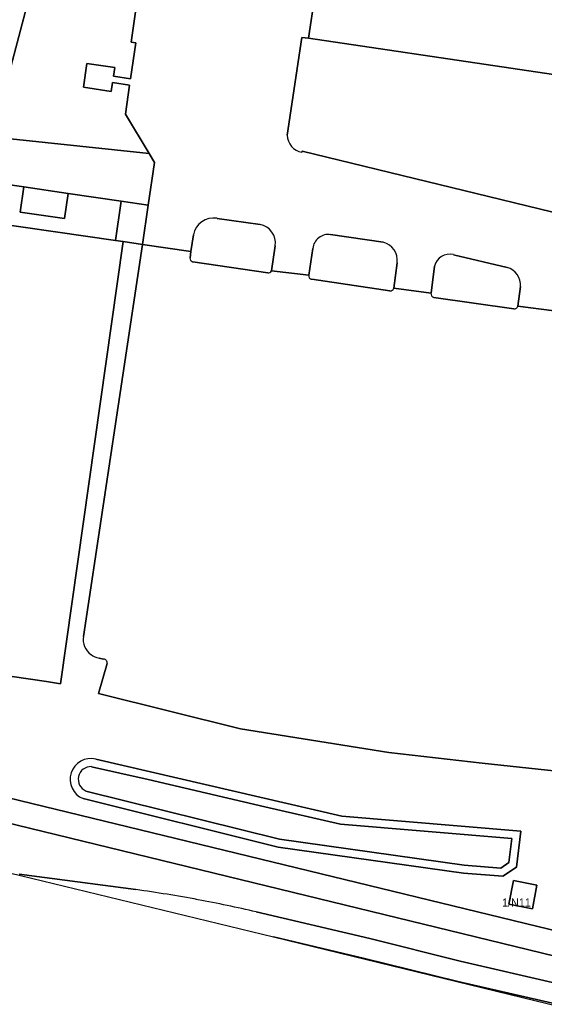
# Model space of a CAD drawing. Extents: x 163043 to 165076, y 382019 to 382874.
# Drawn here: x 164887 to 164952.3, y 382019.4 to 382142.4 of the extents above; entities that cross this region are included whole.
import ezdxf

# ---------------------------------------------------------------- set-up
doc = ezdxf.new("R2010")
doc.units = 0
for name, color, linetype in [('IMGEO_Berm_groen', 7, 'Continuous'), ('IMGEO_Erf', 7, 'Continuous'), ('IMGEO_Fietspad_gesloten', 7, 'Continuous'), ('IMGEO_Groenvoorziening', 7, 'Continuous'), ('IMGEO_Hek', 7, 'Continuous'), ('IMGEO_Oever', 7, 'Continuous'), ('IMGEO_Pand', 7, 'Continuous'), ('IMGEO_Pand_nummerreeks', 7, 'Continuous'), ('IMGEO_Parkeervlak_open', 7, 'Continuous'), ('IMGEO_Rijbaan_lokaal_gesloten', 7, 'Continuous'), ('IMGEO_Rijbaan_lokaal_open', 7, 'Continuous'), ('IMGEO_Verkeerseiland_groen', 7, 'Continuous'), ('IMGEO_Voetpad_open', 7, 'Continuous'), ('IMGEO_Waterloop', 7, 'Continuous')]:
    doc.layers.add(name, color=color, linetype=linetype)

msp = doc.modelspace()

# ---------------------------------------------------------------- linework, layer by layer
at = {"layer": 'IMGEO_Berm_groen'}
for points in [[(164916.45, 382031.48), (164930.58, 382028.18), (164941.81, 382025.37), (164953.88, 382022.57), (164956.12, 382022.19), (164956.22, 382022.18), (164956.8, 382025), (164956.85, 382025.19), (164602.85, 382111.38), (164599.99, 382112.07), (164598.73, 382112.35), (164592.38, 382113.1), (164591, 382106.94)], [(164886.96, 382036.16), (164901.48, 382034.26)], [(164955.57, 382019.38), (164955.65, 382019.7), (164955.47, 382019.72), (164953.3, 382020.13), (164941.52, 382022.81), (164929.91, 382025.67), (164918.61, 382028.36), (164954.36, 382019.67), (164955.57, 382019.38)]]:
    msp.add_lwpolyline(points, dxfattribs=at)
for centre, radius, start, end in [((164878.38, 381867.91), 167.94, 79.4249, 82.0936), ((164878.35, 381867.42), 168.43, 76.9252, 79.4441)]:
    msp.add_arc(centre, radius, start, end, dxfattribs=at)
at = {"layer": 'IMGEO_Erf'}
for points in [[(164884.69, 382132.02), (164887.33, 382141.95), (164891.24, 382156.72), (164892.95, 382163.15), (164895.44, 382168.42), (164899.25, 382173.36), (164897.45, 382173.61), (164897.75, 382175.55), (164892.78, 382176.32), (164891.37, 382170.91), (164884.17, 382143.37)], [(164910.89, 382163.64), (164907.37, 382164.18), (164908.63, 382172.08), (164899.25, 382173.36), (164895.44, 382168.42), (164892.95, 382163.15), (164891.24, 382156.72), (164887.33, 382141.95), (164884.69, 382132.02), (164885.86, 382127.64), (164903.11, 382125.8), (164900.16, 382130.69), (164900.69, 382134.32), (164898.56, 382134.63), (164898.4, 382133.54), (164894.94, 382134.05), (164895.38, 382137.02), (164898.84, 382136.51), (164898.68, 382135.42), (164900.81, 382135.11), (164901.46, 382139.57)], [(164901.46, 382139.57), (164900.87, 382139.65), (164901.63, 382144.87), (164890.74, 382146.43), (164892.91, 382161.18), (164903.55, 382159.66), (164903.4, 382158.01)]]:
    msp.add_lwpolyline(points, dxfattribs=at)
at = {"layer": 'IMGEO_Fietspad_gesloten'}
for points in [[(164885.89, 382036.31), (164887.11, 382036.02), (164918.61, 382028.36)], [(164901.48, 382034.26), (164886.96, 382036.16)], [(164918.61, 382028.36), (164929.91, 382025.67), (164941.52, 382022.81), (164953.3, 382020.13), (164955.47, 382019.72), (164955.65, 382019.7), (164955.72, 382019.69), (164956.32, 382022.17), (164956.22, 382022.18), (164956.12, 382022.19), (164953.88, 382022.57), (164941.81, 382025.37), (164930.58, 382028.18), (164916.45, 382031.48)]]:
    msp.add_lwpolyline(points, dxfattribs=at)
for centre, radius, start, end in [((164878.38, 381867.91), 167.94, 79.4249, 82.0936), ((164878.35, 381867.42), 168.43, 76.9252, 79.4441)]:
    msp.add_arc(centre, radius, start, end, dxfattribs=at)
at = {"layer": 'IMGEO_Groenvoorziening'}
for points in [[(164986.1, 382152.29), (164982.5, 382152.82), (164976.41, 382153.71), (164973.31, 382132.7), (164922.97, 382140.15), (164922.13, 382140.26), (164920.32, 382128.1)], [(164922.13, 382125.97), (164922.16, 382126.1), (164973.33, 382113.68)], [(164899.65, 382119.9), (164893.04, 382120.85), (164892.59, 382117.73), (164887.09, 382118.51), (164887.54, 382121.65), (164882.62, 382122.36)], [(164880.35, 382120.67), (164879.93, 382117.75), (164898.94, 382115), (164899.65, 382119.9)], [(164894.95, 382065.75), (164902.3, 382114.51), (164899.91, 382114.86), (164892.11, 382059.85), (164890.33, 382060.16), (164871.21, 382062.93), (164871.07, 382062.05), (164870.9, 382061.13), (164870.69, 382060.3)], [(164648.88, 382103.16), (164975.4, 382023.88), (164996.47, 382046.06), (164998.31, 382053.98)], [(164970.34, 382047.53), (164968.57, 382047.56), (164961.62, 382048.15), (164944.56, 382049.97), (164932.97, 382051.3), (164914.49, 382054.25), (164896.83, 382058.66), (164897.89, 382062.36)], [(164897.45, 382062.92), (164896.9, 382063.03)], [(164896.49, 382050.48), (164927.09, 382043.38), (164949.37, 382041.52), (164948.84, 382037.04), (164947.13, 382035.91), (164942.23, 382036.3), (164919.16, 382039.55), (164894.91, 382045.57)]]:
    msp.add_lwpolyline(points, dxfattribs=at)
msp.add_lwpolyline([(164951.39, 382034.81), (164950.83, 382031.87), (164947.89, 382032.43), (164948.45, 382035.37)], close=True, dxfattribs=at)
for centre, radius, start, end in [((164922.5, 382128.12), 2.18, 180.633, 260.3961), ((164897.15, 382065.36), 2.24, 169.9106, 235.5071), ((164897.44, 382065.46), 2.49, 231.4441, 257.48), ((164897.42, 382062.45), 0.474, 349.5505, 86.6098), ((164895.88, 382047.97), 2.59, 76.4768, 248.0161)]:
    msp.add_arc(centre, radius, start, end, dxfattribs=at)
at = {"layer": 'IMGEO_Hek'}
for points in [[(164548.87, 382121.27), (164552, 382120.52), (164561.05, 382119.57), (164562.96, 382119.37), (164565.36, 382119.11), (164598.77, 382115.22), (164621.38, 382109.91), (164648.88, 382103.16), (164975.4, 382023.88), (164996.47, 382046.06), (164998.31, 382053.98)], [(164957.04, 382025.14), (164956.85, 382025.19), (164602.85, 382111.38), (164599.99, 382112.07), (164598.73, 382112.35), (164598.36, 382112.35)]]:
    msp.add_lwpolyline(points, dxfattribs=at)
at = {"layer": 'IMGEO_Oever'}
for points in [[(164927.09, 382043.38), (164896.49, 382050.48)], [(164895.96, 382049.54), (164903, 382047.94), (164917.54, 382044.57), (164926.93, 382042.39), (164948.26, 382040.61)], [(164948.26, 382040.61), (164947.9, 382037.62), (164946.87, 382036.94), (164942.34, 382037.29), (164919.35, 382040.54), (164895.26, 382046.51)], [(164894.91, 382045.57), (164919.16, 382039.55), (164942.23, 382036.3), (164947.13, 382035.91), (164948.84, 382037.04), (164949.37, 382041.52), (164927.09, 382043.38)]]:
    msp.add_lwpolyline(points, dxfattribs=at)
for radius, start, end in [(2.59, 76.4768, 248.0161), (1.58, 87.1022, 247.1571)]:
    msp.add_arc((164895.88, 382047.97), radius, start, end, dxfattribs=at)
at = {"layer": 'IMGEO_Pand'}
for points in [[(164981.05, 382185.15), (164982.89, 382197.6), (164983.89, 382204.39), (164933.57, 382211.84), (164933.49, 382211.32), (164930.7, 382192.52), (164928.61, 382178.41), (164928.28, 382176.21), (164912.36, 382178.55), (164910.56, 382166.32), (164917.63, 382165.36), (164918.51, 382164.18), (164919.68, 382165.05), (164925.89, 382164.04), (164926.48, 382163.93), (164923.75, 382145.43), (164922.97, 382140.15), (164973.31, 382132.7), (164976.41, 382153.71), (164977.14, 382158.63)], [(164950.83, 382031.87), (164951.39, 382034.81), (164948.45, 382035.37), (164947.89, 382032.43)]]:
    msp.add_lwpolyline(points, close=True, dxfattribs=at)
at = {"layer": 'IMGEO_Parkeervlak_open'}
msp.add_lwpolyline([(164899.91, 382114.86), (164898.94, 382115), (164879.93, 382117.75), (164874.98, 382118.47), (164870.03, 382119.19), (164864.21, 382079.01), (164862.07, 382064.26), (164868.9, 382063.27), (164871.21, 382062.93), (164890.33, 382060.16), (164892.11, 382059.85)], close=True, dxfattribs=at)
for points in [[(164908.21, 382112.83), (164908.32, 382113.61), (164902.3, 382114.51), (164894.95, 382065.75)], [(164917.9, 382110.97), (164908.58, 382112.33)], [(164922.98, 382110.67), (164918.34, 382111.21)], [(164933.06, 382108.73), (164923.35, 382110.17)], [(164938.2, 382108.43), (164933.57, 382109.07)], [(164948.52, 382106.49), (164938.55, 382107.92)], [(164953.53, 382106.23), (164948.99, 382106.82)], [(164897.89, 382062.36), (164896.83, 382058.66), (164914.49, 382054.25), (164932.97, 382051.3), (164944.56, 382049.97), (164961.62, 382048.15), (164968.57, 382047.56), (164970.34, 382047.53)], [(164896.9, 382063.03), (164897.45, 382062.92)]]:
    msp.add_lwpolyline(points, dxfattribs=at)
for centre, radius, start, end in [((164908.64, 382112.77), 0.438, 171.3193, 261.6835), ((164917.97, 382111.37), 0.405, 259.0794, 335.6832), ((164923.4, 382110.6), 0.427, 169.758, 263.2449), ((164933.11, 382109.2), 0.473, 263.3412, 344.0389), ((164938.64, 382108.36), 0.447, 170.5053, 258.3116), ((164948.59, 382106.89), 0.401, 259.9073, 350.3244), ((164897.15, 382065.36), 2.24, 169.9106, 235.5071), ((164897.44, 382065.46), 2.49, 231.4441, 257.48), ((164897.42, 382062.45), 0.474, 349.5505, 86.6098)]:
    msp.add_arc(centre, radius, start, end, dxfattribs=at)
at = {"layer": 'IMGEO_Rijbaan_lokaal_gesloten'}
for points in [[(164903.11, 382125.8), (164885.86, 382127.64), (164879.36, 382128.34)], [(164882.62, 382122.36), (164887.54, 382121.65), (164893.04, 382120.85), (164899.65, 382119.9), (164903.02, 382119.41), (164903.79, 382124.68), (164903.11, 382125.8)]]:
    msp.add_lwpolyline(points, dxfattribs=at)
at = {"layer": 'IMGEO_Rijbaan_lokaal_open'}
for points in [[(164903.4, 382158.01), (164903.55, 382159.66), (164892.91, 382161.18), (164890.74, 382146.43), (164901.63, 382144.87), (164900.87, 382139.65), (164901.46, 382139.57), (164900.81, 382135.11), (164898.68, 382135.42), (164898.84, 382136.51), (164895.38, 382137.02), (164894.94, 382134.05), (164898.4, 382133.54), (164898.56, 382134.63), (164900.69, 382134.32), (164900.16, 382130.69), (164903.11, 382125.8), (164903.79, 382124.68), (164903.02, 382119.41), (164902.3, 382114.51), (164908.32, 382113.61), (164908.64, 382115.69)], [(164920.32, 382128.1), (164922.13, 382140.26), (164922.97, 382140.15), (164923.75, 382145.43), (164920.68, 382145.89), (164922.7, 382159.54)], [(164971.38, 382105.93), (164973.33, 382113.68), (164922.16, 382126.1), (164922.13, 382125.97)], [(164911.57, 382117.74), (164916.93, 382116.98)], [(164925.71, 382115.72), (164932.23, 382114.78)], [(164918.8, 382114.35), (164918.34, 382111.21), (164922.98, 382110.67), (164923.48, 382114.02)], [(164940.99, 382113.23), (164947.67, 382111.65)], [(164933.99, 382112.22), (164933.57, 382109.07), (164938.2, 382108.43), (164938.64, 382111.8)], [(164949.35, 382109.27), (164948.99, 382106.82), (164953.53, 382106.23), (164953.8, 382107.93)]]:
    msp.add_lwpolyline(points, dxfattribs=at)
for centre, radius, start, end in [((164922.5, 382128.12), 2.18, 180.633, 260.3961), ((164911.14, 382115.24), 2.55, 80.3337, 169.6319), ((164916.51, 382114.71), 2.32, 351.0322, 79.6107), ((164925.4, 382113.82), 1.92, 80.681, 174.2919), ((164931.73, 382112.55), 2.28, 351.5603, 77.3941), ((164940.54, 382111.34), 1.95, 76.5139, 166.4855), ((164947.01, 382109.39), 2.35, 356.8616, 73.5736)]:
    msp.add_arc(centre, radius, start, end, dxfattribs=at)
at = {"layer": 'IMGEO_Verkeerseiland_groen'}
for points in [[(164916.93, 382116.98), (164911.57, 382117.74)], [(164908.64, 382115.69), (164908.32, 382113.61), (164908.21, 382112.83)], [(164932.23, 382114.78), (164925.71, 382115.72)], [(164918.34, 382111.21), (164918.8, 382114.35)], [(164923.48, 382114.02), (164922.98, 382110.67)], [(164947.67, 382111.65), (164940.99, 382113.23)], [(164908.58, 382112.33), (164917.9, 382110.97)], [(164933.57, 382109.07), (164933.99, 382112.22)], [(164938.64, 382111.8), (164938.2, 382108.43)], [(164923.35, 382110.17), (164933.06, 382108.73)], [(164948.99, 382106.82), (164949.35, 382109.27)], [(164938.55, 382107.92), (164948.52, 382106.49)]]:
    msp.add_lwpolyline(points, dxfattribs=at)
for centre, radius, start, end in [((164911.14, 382115.24), 2.55, 80.3337, 169.6319), ((164916.51, 382114.71), 2.32, 351.0322, 79.6107), ((164925.4, 382113.82), 1.92, 80.681, 174.2919), ((164931.73, 382112.55), 2.28, 351.5603, 77.3941), ((164908.64, 382112.77), 0.438, 171.3193, 261.6835), ((164940.54, 382111.34), 1.95, 76.5139, 166.4855), ((164947.01, 382109.39), 2.35, 356.8616, 73.5736), ((164917.97, 382111.37), 0.405, 259.0794, 335.6832), ((164923.4, 382110.6), 0.427, 169.758, 263.2449), ((164933.11, 382109.2), 0.473, 263.3412, 344.0389), ((164938.64, 382108.36), 0.447, 170.5053, 258.3116), ((164948.59, 382106.89), 0.401, 259.9073, 350.3244)]:
    msp.add_arc(centre, radius, start, end, dxfattribs=at)
at = {"layer": 'IMGEO_Voetpad_open'}
for points in [[(164893.04, 382120.85), (164887.54, 382121.65), (164887.09, 382118.51), (164892.59, 382117.73)], [(164903.02, 382119.41), (164899.65, 382119.9), (164898.94, 382115), (164899.91, 382114.86), (164902.3, 382114.51)]]:
    msp.add_lwpolyline(points, close=True, dxfattribs=at)
msp.add_lwpolyline([(164602.85, 382111.38), (164956.85, 382025.19), (164957.04, 382025.14), (164976.47, 382020.39), (164998.3, 382044.35), (165000, 382051.49), (165013.15, 382106.77), (165010.7, 382107.34), (164998.76, 382055.9), (164998.52, 382054.86), (164998.31, 382053.98), (164996.47, 382046.06), (164975.4, 382023.88), (164648.88, 382103.16)], dxfattribs=at)
at = {"layer": 'IMGEO_Waterloop'}
for points in [[(164948.26, 382040.61), (164926.93, 382042.39), (164917.54, 382044.57), (164903, 382047.94), (164895.96, 382049.54)], [(164895.26, 382046.51), (164919.35, 382040.54), (164942.34, 382037.29), (164946.87, 382036.94), (164947.9, 382037.62), (164948.26, 382040.61)]]:
    msp.add_lwpolyline(points, dxfattribs=at)
msp.add_arc((164895.88, 382047.97), 1.58, 87.1022, 247.1571, dxfattribs=at)

# ---------------------------------------------------------------- texts
at = {"layer": 'IMGEO_Pand_nummerreeks'}
msp.add_text('1/N11', height=1, dxfattribs=at).set_placement((164947.05, 382032.15))

doc.saveas('drawing.dxf')
